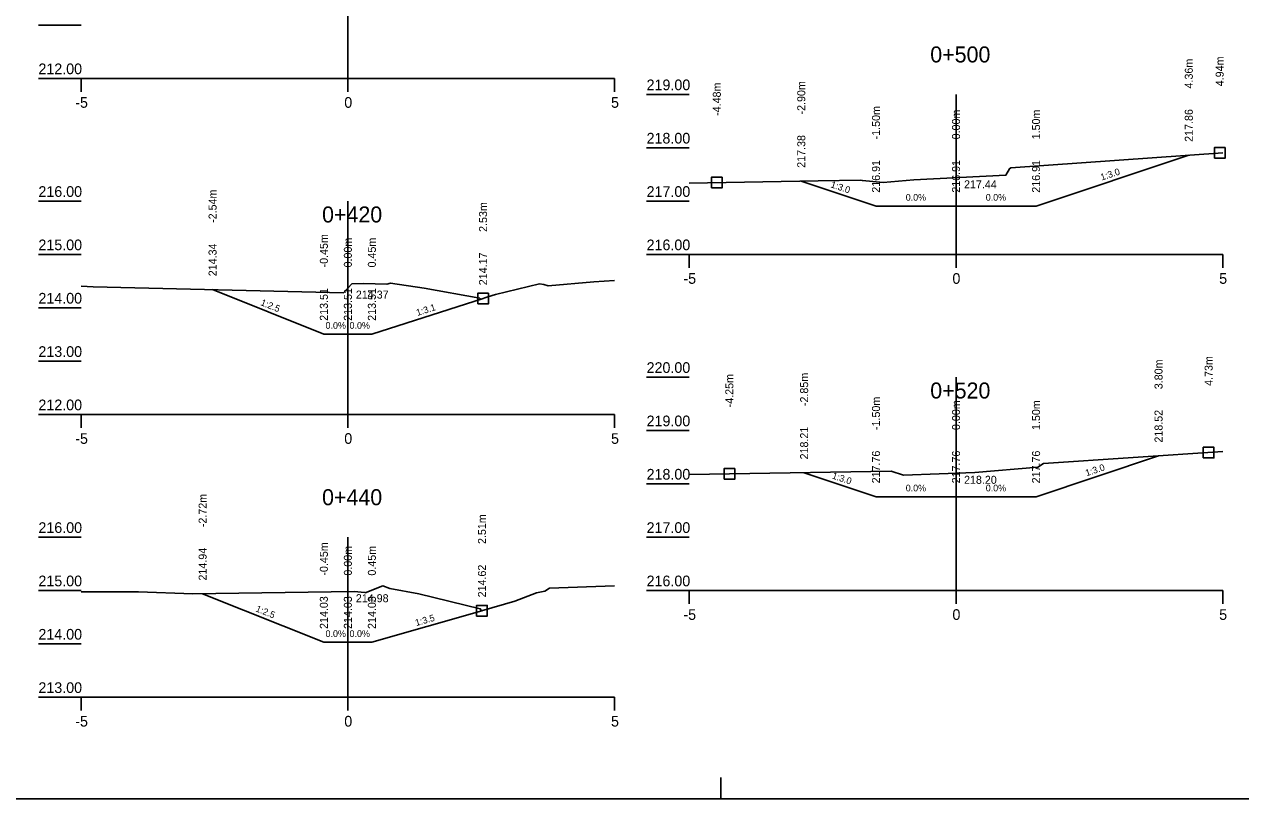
# Model space of a CAD drawing. Extents: x -577315 to -577212, y -1159820 to -1159790.
# Drawn here: x -577267.41 to -577244.61, y -1159820.05 to -1159805.53 of the extents above; entities that cross this region are included whole.
import ezdxf

# ---------------------------------------------------------------- set-up
doc = ezdxf.new("R2010")
doc.units = 0
for name, color, linetype in [('16', 7, 'Continuous'), ('21', 7, 'Continuous'), ('28', 7, 'Continuous'), ('59', 7, 'Continuous'), ('Body pricny rez', 7, 'Continuous'), ('Hranice_pozemku', 7, 'Continuous'), ('Popis pricneho profilu', 7, 'Continuous'), ('Rámy', 7, 'Continuous')]:
    doc.layers.add(name, color=color, linetype=linetype)

msp = doc.modelspace()

# ---------------------------------------------------------------- linework, layer by layer
for points in [[(-577254.943, -1159808.51), (-577252.525, -1159808.468), (-577251.736, -1159808.453), (-577251.699, -1159808.464), (-577251.306, -1159808.499), (-577250.736, -1159808.452), (-577249.009, -1159808.359), (-577248.94, -1159808.243), (-577248.918, -1159808.227), (-577248.914, -1159808.226), (-577244.943, -1159807.941)], [(-577248.443, -1159808.941), (-577245.58, -1159807.987)], [(-577251.443, -1159808.941), (-577252.844, -1159808.474)], [(-577251.443, -1159808.941), (-577249.943, -1159808.941), (-577248.443, -1159808.941)], [(-577266.343, -1159810.445), (-577266.119, -1159810.455), (-577261.426, -1159810.565), (-577261.268, -1159810.398), (-577261.051, -1159810.396), (-577260.615, -1159810.407), (-577260.544, -1159810.388), (-577259.911, -1159810.482), (-577258.872, -1159810.67), (-577258.86, -1159810.695), (-577258.72, -1159810.641), (-577258.578, -1159810.597), (-577257.75, -1159810.401), (-577257.669, -1159810.413), (-577257.59, -1159810.435), (-577256.732, -1159810.36), (-577256.343, -1159810.336)], [(-577261.793, -1159811.342), (-577263.879, -1159810.507)], [(-577260.893, -1159811.342), (-577258.809, -1159810.676)], [(-577261.793, -1159811.342), (-577261.343, -1159811.342), (-577260.893, -1159811.342)], [(-577254.943, -1159813.976), (-577251.158, -1159813.914), (-577250.929, -1159813.984), (-577249.591, -1159813.935), (-577248.409, -1159813.838), (-577248.303, -1159813.769), (-577244.943, -1159813.544)], [(-577248.443, -1159814.39), (-577246.147, -1159813.625)], [(-577251.443, -1159814.39), (-577252.79, -1159813.941)], [(-577251.443, -1159814.39), (-577249.943, -1159814.39), (-577248.443, -1159814.39)], [(-577266.343, -1159816.172), (-577265.268, -1159816.171), (-577264.247, -1159816.213), (-577261.224, -1159816.166), (-577261.022, -1159816.183), (-577261.016, -1159816.189), (-577260.688, -1159816.061), (-577260.556, -1159816.108), (-577260.014, -1159816.209), (-577258.862, -1159816.49), (-577258.841, -1159816.531), (-577258.213, -1159816.348), (-577257.805, -1159816.189), (-577257.652, -1159816.16), (-577257.561, -1159816.102), (-577256.343, -1159816.059)], [(-577261.793, -1159817.119), (-577264.065, -1159816.211)], [(-577260.893, -1159817.119), (-577258.829, -1159816.527)], [(-577261.793, -1159817.119), (-577261.343, -1159817.119), (-577260.893, -1159817.119)]]:
    msp.add_lwpolyline(points)
at = {"layer": '16'}
for p, q in [((-577266.343, -1159806.549), (-577256.343, -1159806.549)), ((-577254.943, -1159809.849), (-577244.943, -1159809.849)), ((-577266.343, -1159812.849), (-577256.343, -1159812.849)), ((-577254.943, -1159816.149), (-577244.943, -1159816.149)), ((-577266.343, -1159818.149), (-577256.343, -1159818.149))]:
    msp.add_line(p, q, dxfattribs=at)
at = {"layer": '21'}
for p, q in [((-577267.143, -1159805.549), (-577266.343, -1159805.549)), ((-577267.143, -1159806.549), (-577266.343, -1159806.549)), ((-577255.743, -1159806.849), (-577254.943, -1159806.849)), ((-577255.743, -1159807.849), (-577254.943, -1159807.849)), ((-577267.143, -1159808.849), (-577266.343, -1159808.849)), ((-577255.743, -1159808.849), (-577254.943, -1159808.849)), ((-577267.143, -1159809.849), (-577266.343, -1159809.849)), ((-577255.743, -1159809.849), (-577254.943, -1159809.849)), ((-577267.143, -1159810.849), (-577266.343, -1159810.849)), ((-577267.143, -1159811.849), (-577266.343, -1159811.849)), ((-577255.743, -1159812.149), (-577254.943, -1159812.149)), ((-577267.143, -1159812.849), (-577266.343, -1159812.849)), ((-577255.743, -1159813.149), (-577254.943, -1159813.149)), ((-577255.743, -1159814.149), (-577254.943, -1159814.149)), ((-577267.143, -1159815.149), (-577266.343, -1159815.149)), ((-577255.743, -1159815.149), (-577254.943, -1159815.149)), ((-577267.143, -1159816.149), (-577266.343, -1159816.149)), ((-577255.743, -1159816.149), (-577254.943, -1159816.149)), ((-577267.143, -1159817.149), (-577266.343, -1159817.149)), ((-577267.143, -1159818.149), (-577266.343, -1159818.149))]:
    msp.add_line(p, q, dxfattribs=at)
at = {"layer": '28'}
for p, q in [((-577261.343, -1159803.549), (-577261.343, -1159806.549)), ((-577249.943, -1159806.849), (-577249.943, -1159809.849)), ((-577261.343, -1159808.849), (-577261.343, -1159812.849)), ((-577249.943, -1159812.149), (-577249.943, -1159816.149)), ((-577261.343, -1159815.149), (-577261.343, -1159818.149))]:
    msp.add_line(p, q, dxfattribs=at)
at = {"layer": '59'}
for p, q in [((-577266.343, -1159806.799), (-577266.343, -1159806.549)), ((-577261.343, -1159806.799), (-577261.343, -1159806.549)), ((-577256.343, -1159806.799), (-577256.343, -1159806.549)), ((-577254.943, -1159810.099), (-577254.943, -1159809.849)), ((-577249.943, -1159810.099), (-577249.943, -1159809.849)), ((-577244.943, -1159810.099), (-577244.943, -1159809.849)), ((-577266.343, -1159813.099), (-577266.343, -1159812.849)), ((-577261.343, -1159813.099), (-577261.343, -1159812.849)), ((-577256.343, -1159813.099), (-577256.343, -1159812.849)), ((-577254.943, -1159816.399), (-577254.943, -1159816.149)), ((-577249.943, -1159816.399), (-577249.943, -1159816.149)), ((-577244.943, -1159816.399), (-577244.943, -1159816.149)), ((-577266.343, -1159818.399), (-577266.343, -1159818.149)), ((-577261.343, -1159818.399), (-577261.343, -1159818.149)), ((-577256.343, -1159818.399), (-577256.343, -1159818.149))]:
    msp.add_line(p, q, dxfattribs=at)
at = {"layer": 'Hranice_pozemku'}
for points in [[(-577245.101, -1159808.045), (-577244.901, -1159808.045), (-577244.901, -1159807.845), (-577245.101, -1159807.845)], [(-577254.527, -1159808.601), (-577254.327, -1159808.601), (-577254.327, -1159808.401), (-577254.527, -1159808.401)], [(-577258.909, -1159810.776), (-577258.709, -1159810.776), (-577258.709, -1159810.576), (-577258.909, -1159810.576)], [(-577245.308, -1159813.662), (-577245.108, -1159813.662), (-577245.108, -1159813.462), (-577245.308, -1159813.462)], [(-577254.292, -1159814.064), (-577254.092, -1159814.064), (-577254.092, -1159813.864), (-577254.292, -1159813.864)], [(-577258.929, -1159816.627), (-577258.729, -1159816.627), (-577258.729, -1159816.427), (-577258.929, -1159816.427)]]:
    msp.add_lwpolyline(points, close=True, dxfattribs=at)
at = {"layer": 'Rámy'}
msp.add_line((-577254.353, -1159820.051), (-577254.353, -1159819.651), dxfattribs=at)
msp.add_lwpolyline([(-577315.23, -1159790.351), (-577212.353, -1159790.351), (-577212.353, -1159820.051), (-577315.23, -1159820.051)], close=True, dxfattribs=at)

# ---------------------------------------------------------------- texts
for s, height, p in [('0+500', 0.3, (-577250.426, -1159806.249)), ('0+420', 0.3, (-577261.826, -1159809.249)), ('+', 0.001, (-577249.943, -1159808.941)), ('+', 0.001, (-577261.343, -1159811.342)), ('0+520', 0.3, (-577250.426, -1159812.549)), ('0+440', 0.3, (-577261.826, -1159814.549)), ('+', 0.001, (-577249.943, -1159814.391)), ('+', 0.001, (-577261.343, -1159817.12))]:
    msp.add_text(s, height=height).set_placement(p)
for s, rotation, p in [('1:3.0', 18.4349, (-577247.211, -1159808.464)), ('1:3.0', 341.5651, (-577252.304, -1159808.588)), ('1:2.5', 338.1986, (-577262.99, -1159810.796)), ('1:3.1', 17.7329, (-577260.039, -1159811.003)), ('1:3.0', 18.4349, (-577247.495, -1159814.008)), ('1:3.0', 341.5651, (-577252.277, -1159814.046)), ('1:2.5', 338.1986, (-577263.082, -1159816.536)), ('1:3.5', 16.0035, (-577260.061, -1159816.816))]:
    msp.add_text(s, height=0.125, rotation=rotation).set_placement(p)
at = {"layer": '16'}
for p in [(-577250.886, -1159808.841), (-577249.386, -1159808.841), (-577261.761, -1159811.242), (-577261.311, -1159811.242), (-577250.886, -1159814.29), (-577249.386, -1159814.29), (-577261.761, -1159817.019), (-577261.311, -1159817.019)]:
    msp.add_text('0.0%', height=0.125, rotation=360, dxfattribs=at).set_placement(p)
at = {"layer": '21'}
for s, p in [('212.00', (-577267.143, -1159806.469)), ('219.00', (-577255.743, -1159806.769)), ('-5', (-577266.453, -1159807.099)), ('0', (-577261.41, -1159807.099)), ('5', (-577256.41, -1159807.099)), ('218.00', (-577255.743, -1159807.769)), ('216.00', (-577267.143, -1159808.769)), ('217.00', (-577255.743, -1159808.769)), ('215.00', (-577267.143, -1159809.769)), ('216.00', (-577255.743, -1159809.769)), ('-5', (-577255.053, -1159810.399)), ('0', (-577250.01, -1159810.399)), ('5', (-577245.01, -1159810.399)), ('214.00', (-577267.143, -1159810.769)), ('213.00', (-577267.143, -1159811.769)), ('220.00', (-577255.743, -1159812.069)), ('212.00', (-577267.143, -1159812.769)), ('219.00', (-577255.743, -1159813.069)), ('-5', (-577266.453, -1159813.399)), ('0', (-577261.41, -1159813.399)), ('5', (-577256.41, -1159813.399)), ('218.00', (-577255.743, -1159814.069)), ('216.00', (-577267.143, -1159815.069)), ('217.00', (-577255.743, -1159815.069)), ('215.00', (-577267.143, -1159816.069)), ('216.00', (-577255.743, -1159816.069)), ('-5', (-577255.053, -1159816.699)), ('0', (-577250.01, -1159816.699)), ('5', (-577245.01, -1159816.699)), ('214.00', (-577267.143, -1159817.069)), ('213.00', (-577267.143, -1159818.069)), ('-5', (-577266.453, -1159818.699)), ('0', (-577261.41, -1159818.699)), ('5', (-577256.41, -1159818.699))]:
    msp.add_text(s, height=0.2, dxfattribs=at).set_placement(p)
at = {"layer": '59'}
for s, p in [('217.44', (-577249.793, -1159808.609)), ('214.37', (-577261.193, -1159810.676)), ('218.20', (-577249.793, -1159814.148)), ('214.98', (-577261.193, -1159816.368))]:
    msp.add_text(s, height=0.15, dxfattribs=at).set_placement(p)
at = {"layer": 'Body pricny rez'}
for p in [(-577245.581, -1159807.987), (-577252.844, -1159808.474), (-577251.443, -1159808.941), (-577248.443, -1159808.941), (-577263.879, -1159810.508), (-577258.809, -1159810.676), (-577261.793, -1159811.342), (-577260.893, -1159811.342), (-577246.148, -1159813.625), (-577252.79, -1159813.941), (-577251.443, -1159814.391), (-577248.443, -1159814.391), (-577264.065, -1159816.211), (-577258.829, -1159816.528), (-577261.793, -1159817.12), (-577260.893, -1159817.12)]:
    msp.add_text('+', height=0.001, dxfattribs=at).set_placement(p)
at = {"layer": 'Popis pricneho profilu'}
for s, p in [('4.36m', (-577245.505, -1159806.737)), ('4.94m', (-577244.926, -1159806.695)), ('4.94m', (-577244.926, -1159806.695)), ('-4.48m', (-577254.352, -1159807.251)), ('-4.48m', (-577254.352, -1159807.251)), ('-2.90m', (-577252.769, -1159807.224)), ('-1.50m', (-577251.368, -1159807.691)), ('0.00m', (-577249.868, -1159807.691)), ('1.50m', (-577248.368, -1159807.691)), ('217.86', (-577245.505, -1159807.737)), ('217.38', (-577252.769, -1159808.224)), ('216.91', (-577251.368, -1159808.691)), ('216.91', (-577249.868, -1159808.691)), ('216.91', (-577248.368, -1159808.691)), ('-2.54m', (-577263.804, -1159809.257)), ('2.53m', (-577258.734, -1159809.426)), ('2.53m', (-577258.734, -1159809.426)), ('2.53m', (-577258.734, -1159809.426)), ('-0.45m', (-577261.718, -1159810.092)), ('0.00m', (-577261.268, -1159810.092)), ('0.45m', (-577260.818, -1159810.092)), ('214.34', (-577263.804, -1159810.257)), ('214.17', (-577258.734, -1159810.426)), ('213.51', (-577261.718, -1159811.092)), ('213.51', (-577261.268, -1159811.092)), ('213.51', (-577260.818, -1159811.092)), ('3.80m', (-577246.072, -1159812.375)), ('4.73m', (-577245.133, -1159812.312)), ('4.73m', (-577245.133, -1159812.312)), ('-4.25m', (-577254.117, -1159812.714)), ('-4.25m', (-577254.117, -1159812.714)), ('-2.85m', (-577252.715, -1159812.691)), ('-1.50m', (-577251.368, -1159813.14)), ('0.00m', (-577249.868, -1159813.14)), ('1.50m', (-577248.368, -1159813.14)), ('218.52', (-577246.072, -1159813.375)), ('218.21', (-577252.715, -1159813.691)), ('217.76', (-577251.368, -1159814.14)), ('217.76', (-577249.868, -1159814.14)), ('217.76', (-577248.368, -1159814.14)), ('-2.72m', (-577263.99, -1159814.961)), ('2.51m', (-577258.754, -1159815.277)), ('2.51m', (-577258.754, -1159815.277)), ('2.51m', (-577258.754, -1159815.277)), ('214.94', (-577263.99, -1159815.961)), ('-0.45m', (-577261.718, -1159815.869)), ('0.00m', (-577261.268, -1159815.869)), ('0.45m', (-577260.818, -1159815.869)), ('214.62', (-577258.754, -1159816.277)), ('214.03', (-577261.718, -1159816.869)), ('214.03', (-577261.268, -1159816.869)), ('214.03', (-577260.818, -1159816.869))]:
    msp.add_text(s, height=0.15, rotation=90, dxfattribs=at).set_placement(p)

doc.saveas('drawing.dxf')
